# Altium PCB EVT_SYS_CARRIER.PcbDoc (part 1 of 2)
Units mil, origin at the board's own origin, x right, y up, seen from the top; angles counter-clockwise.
Board outline 3543.31 x 2755.91 mil, 4 copper layers (Top Layer, Mid-Layer 1, Mid-Layer 2, Bottom Layer), stack 63.036 mil thick; 105 components, 66 nets, 607 pads, 200 vias.
Unrouted connection lines stored in the file: 138.
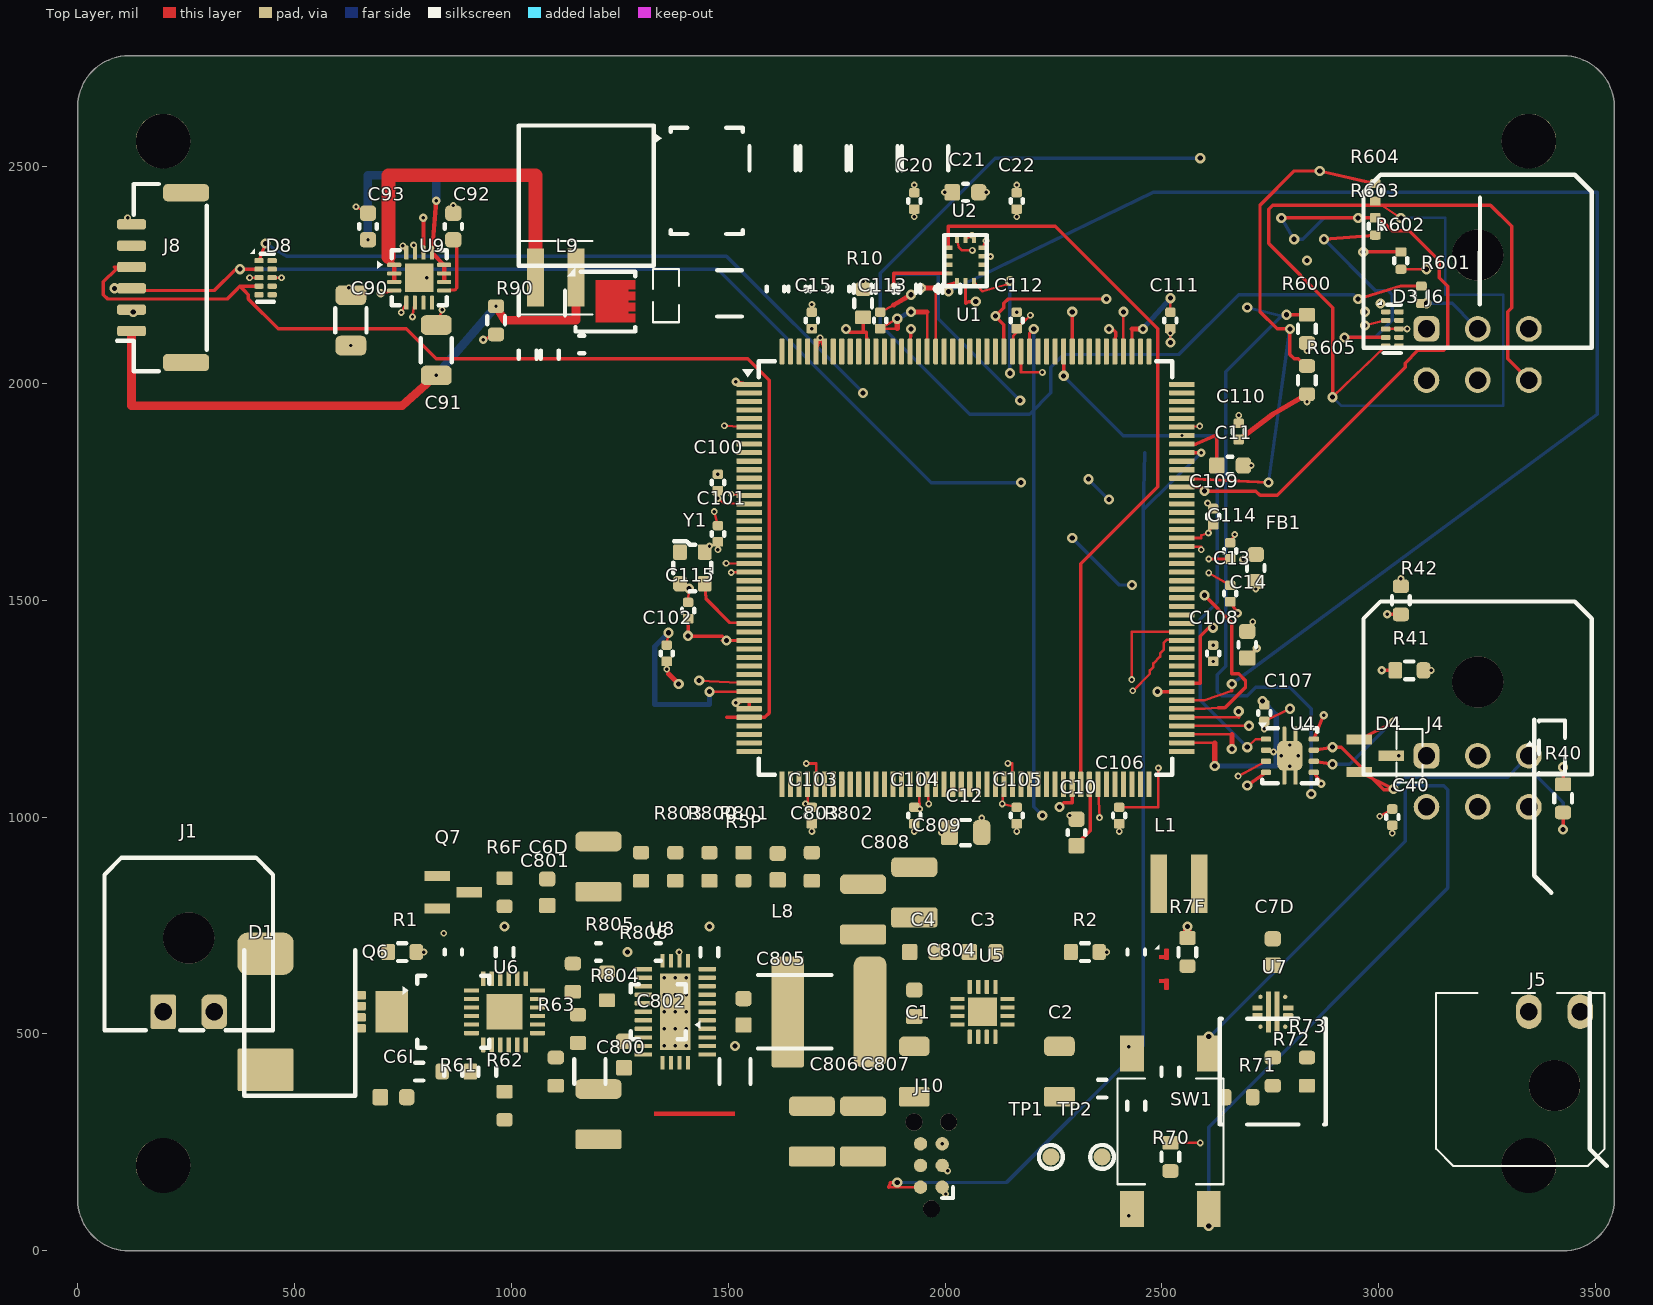
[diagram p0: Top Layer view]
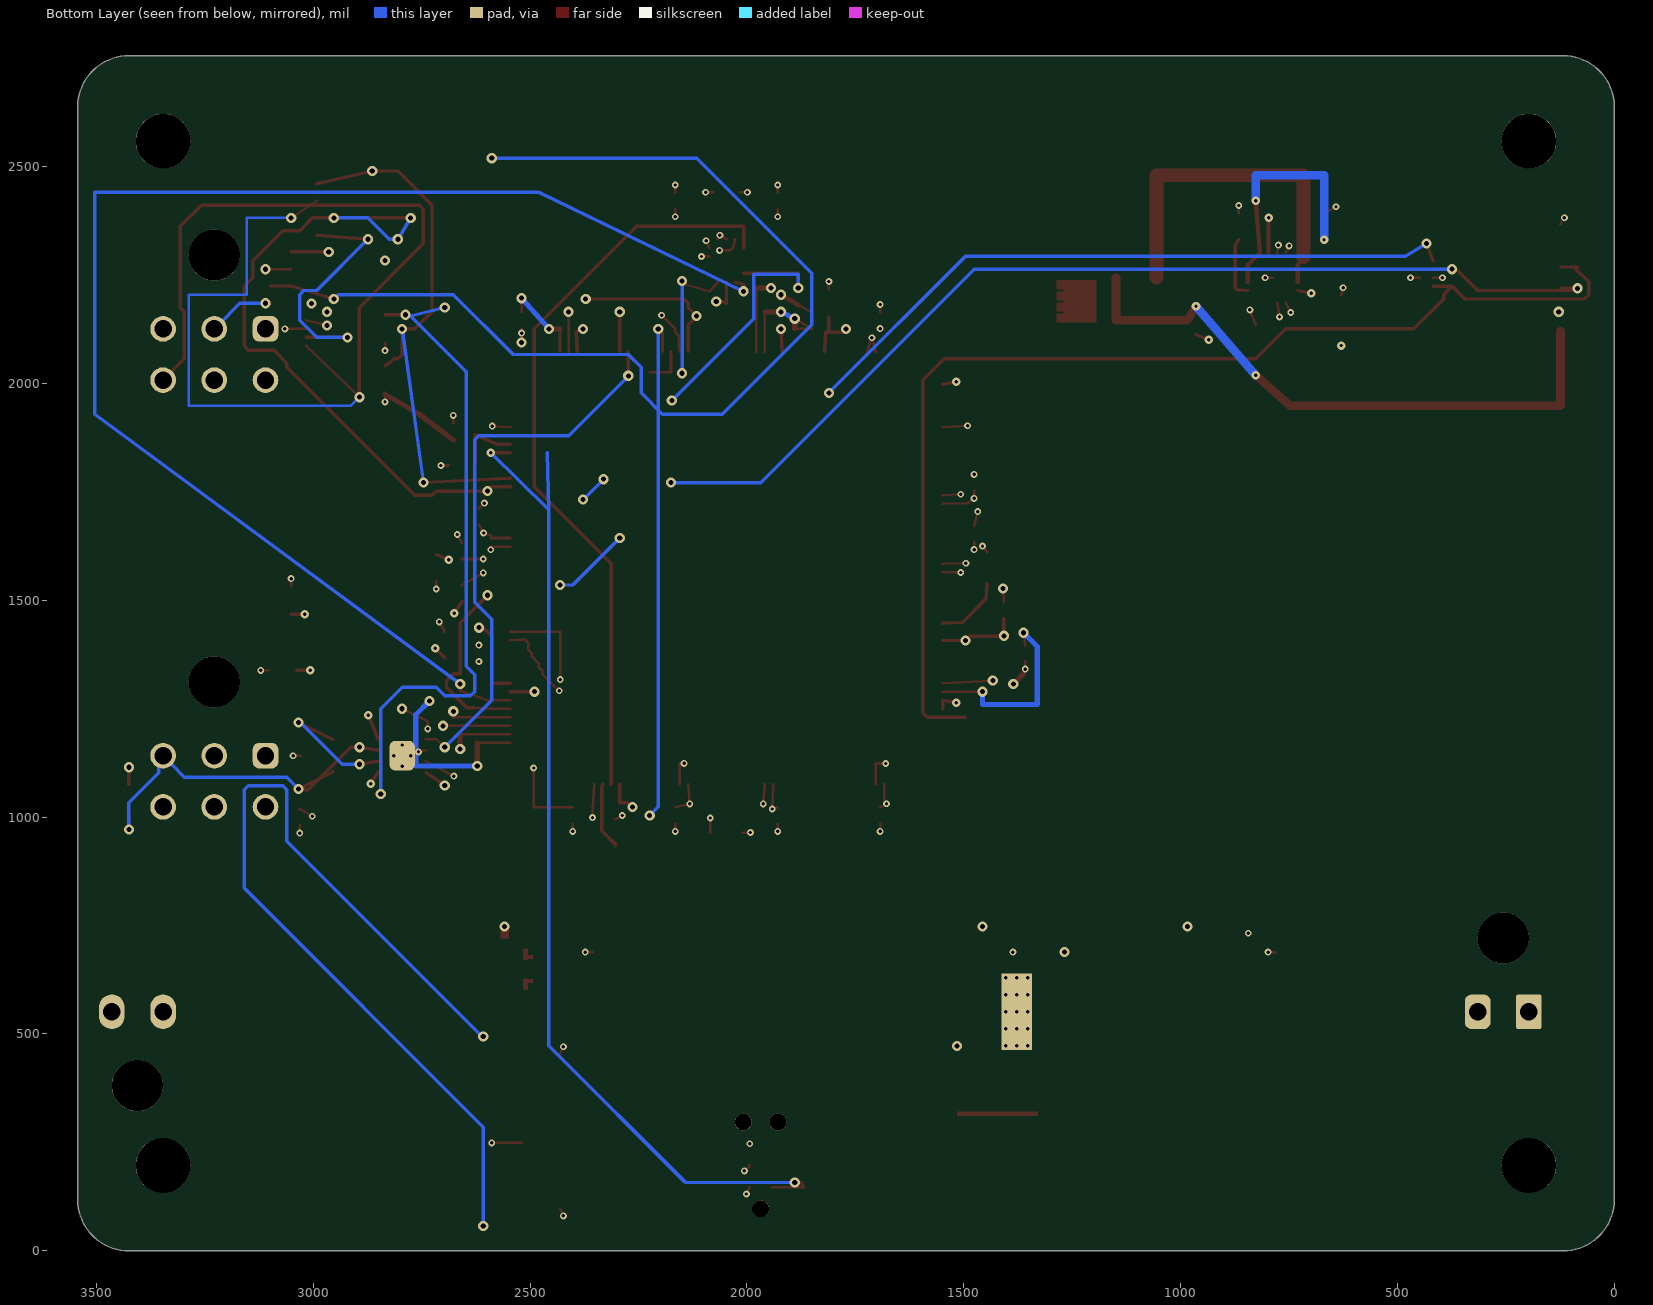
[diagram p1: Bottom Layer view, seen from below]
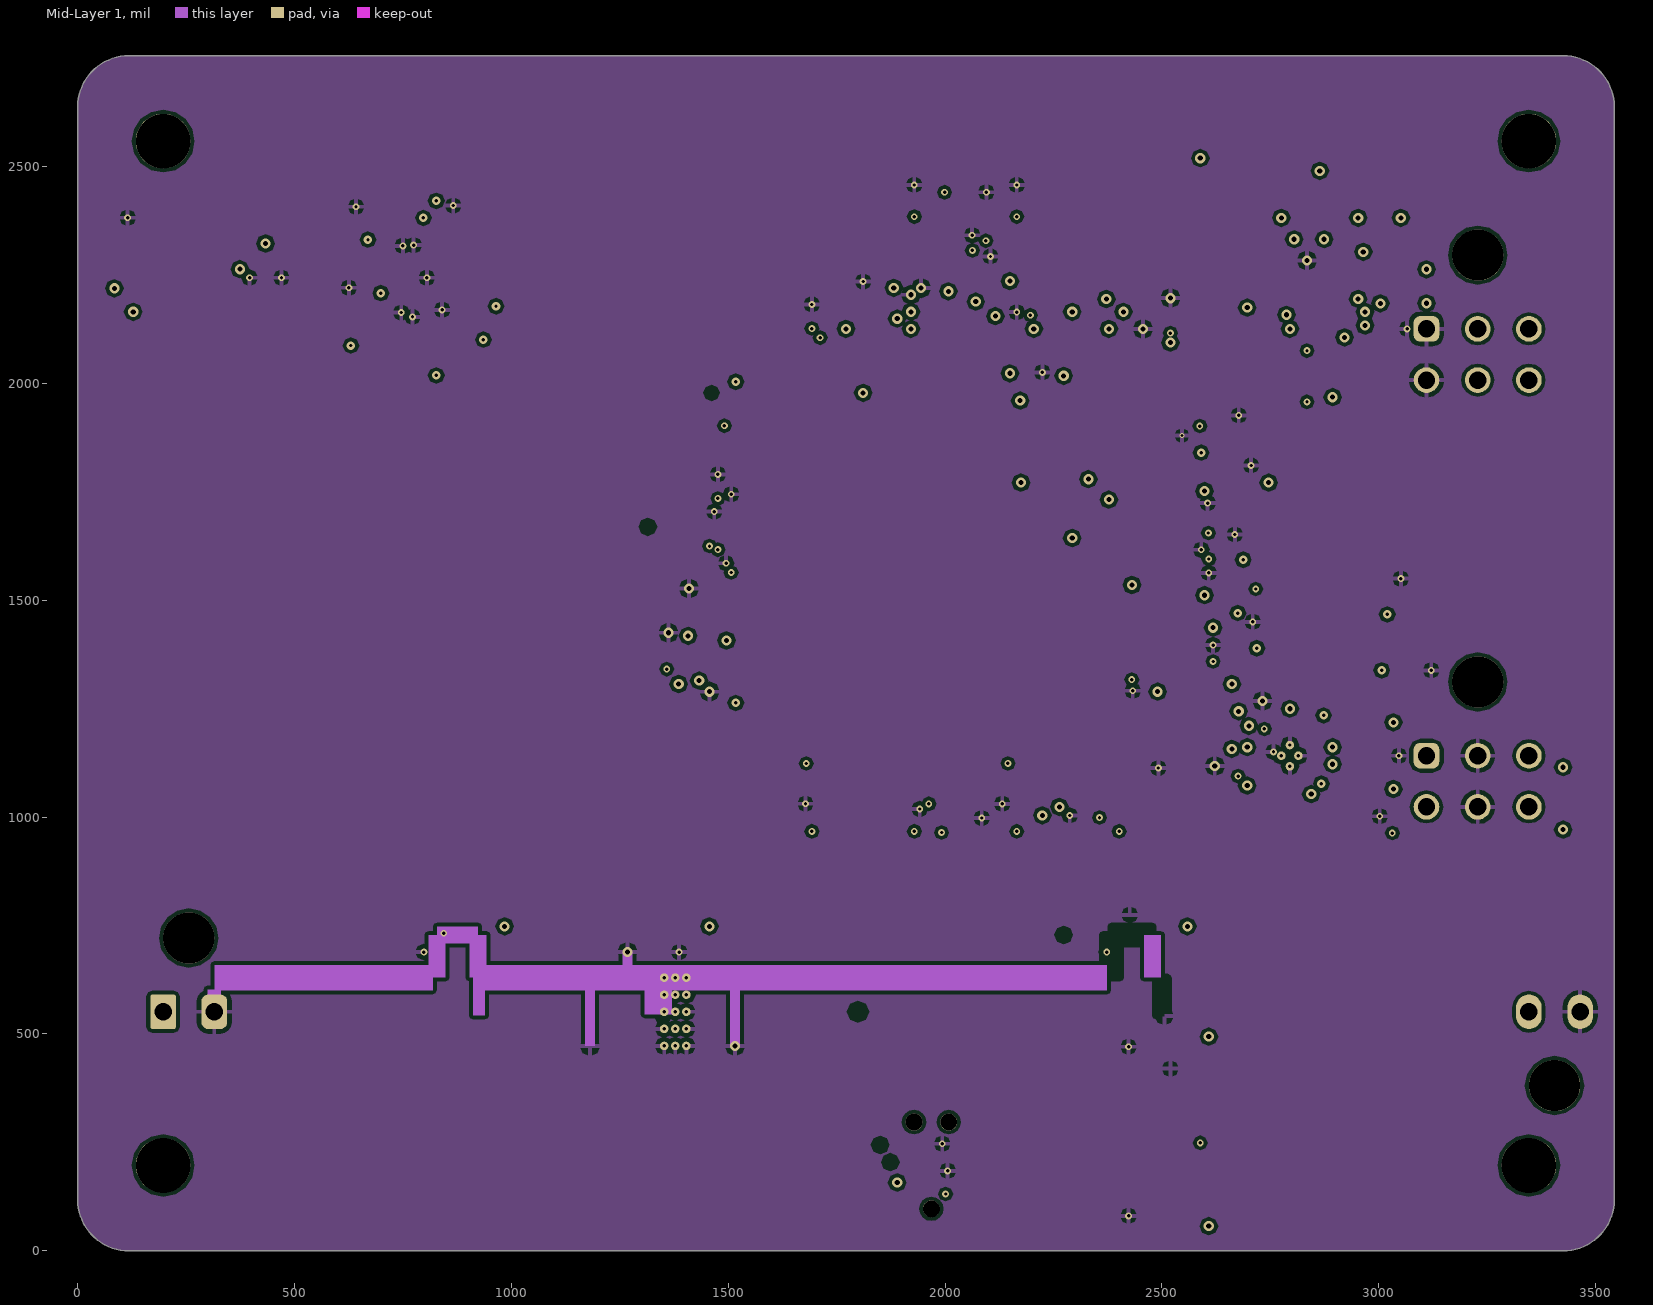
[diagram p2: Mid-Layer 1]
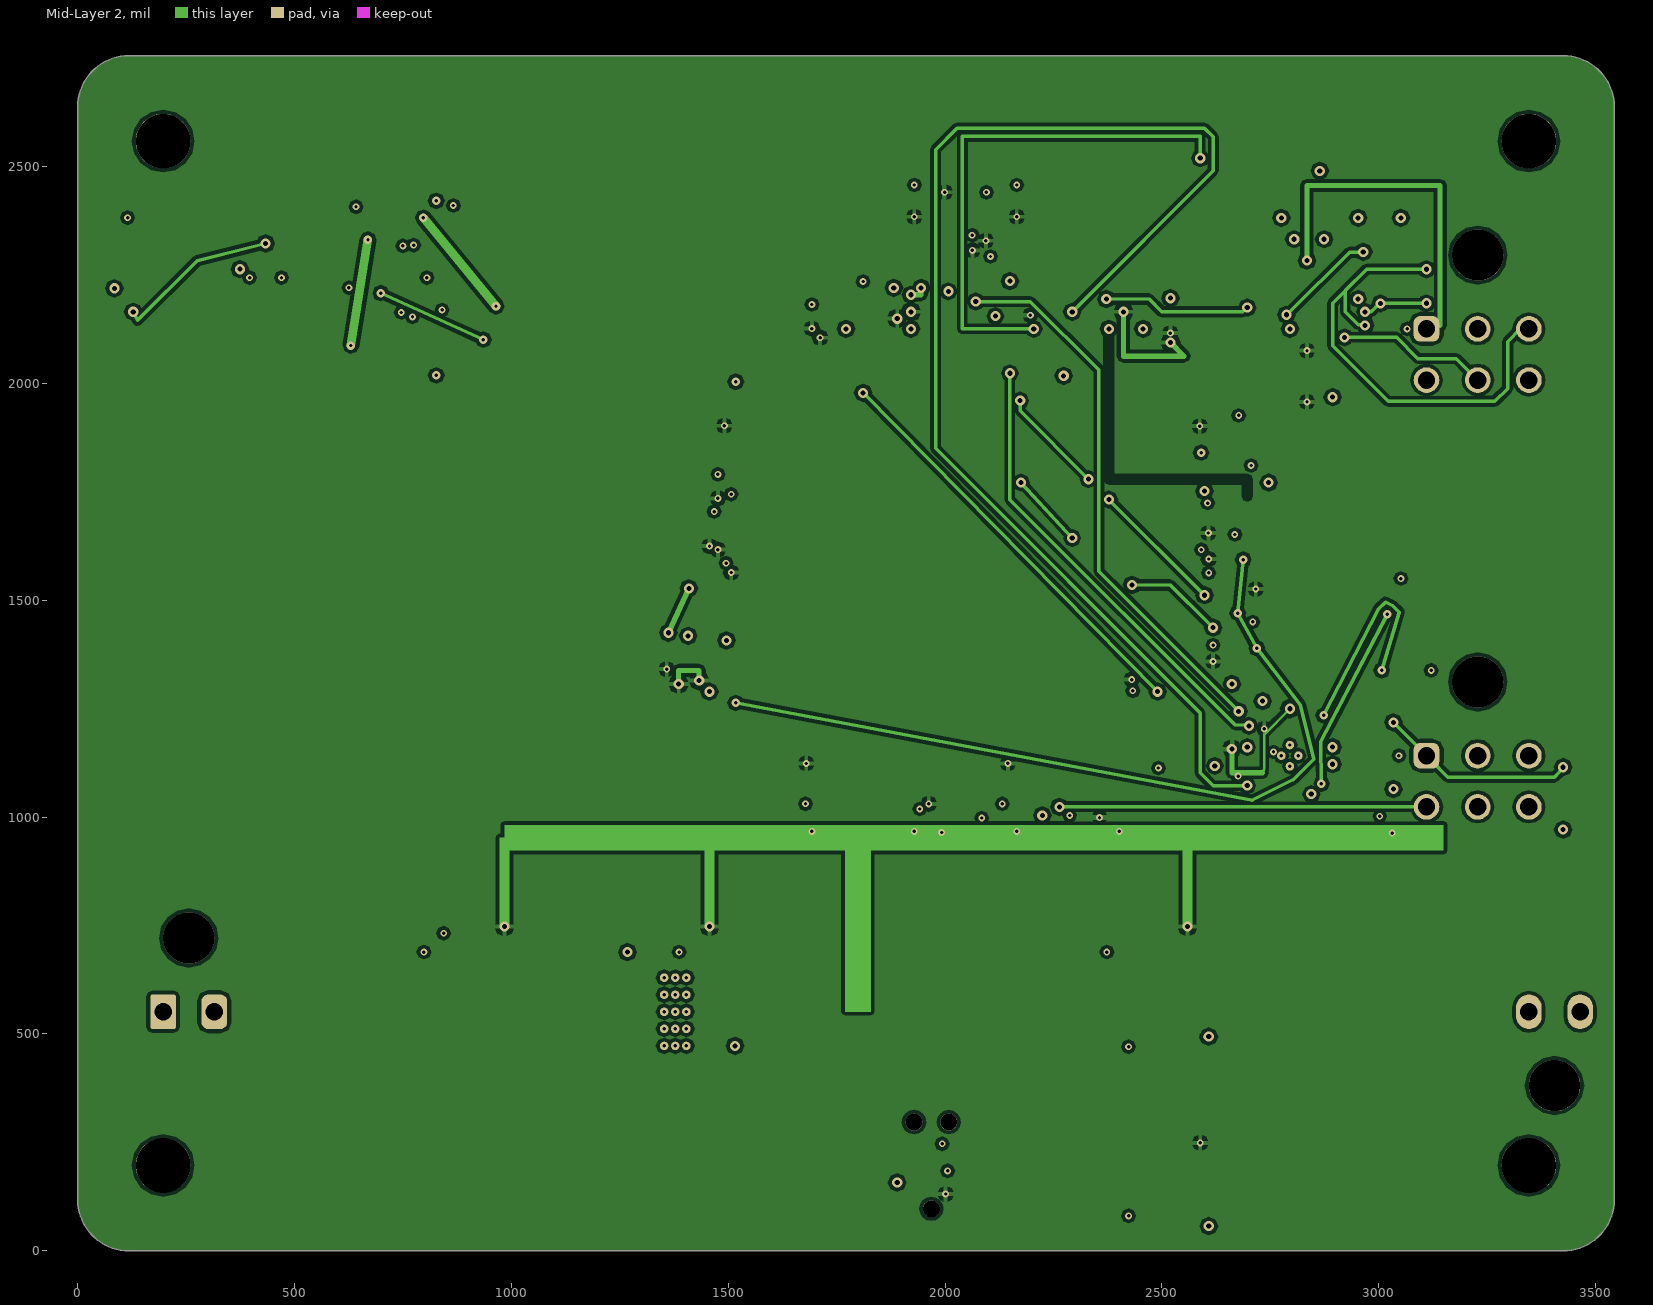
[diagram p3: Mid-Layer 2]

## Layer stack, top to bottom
Top Solder: solder mask 0.4, Solder Resist, Dk 3.5
Top Layer: signal copper 1.4
Dielectric 2: prepreg 7.0866, PP-006, Dk 4.2
Mid-Layer 1: signal copper 1.378
Dielectric 1: dielectric 43.3071, FR-4, Dk 4.2
Mid-Layer 2: signal copper 1.378
Dielectric 3: prepreg 7.0866, PP-006, Dk 4.2
Bottom Layer: signal copper 1.4
Bottom Solder: solder mask 0.4, Solder Resist, Dk 3.5

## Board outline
118.11,0 cw(c118.11,118.11) 0,118.11 0,2637.8 cw(c118.11,2637.8) 118.11,2755.91 3425.2,2755.91 cw(c3425.2,2637.8) 3543.31,2637.8 3543.31,118.11 cw(c3425.2,118.11) 3425.2,0

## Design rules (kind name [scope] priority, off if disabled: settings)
Clearance R_UART_TO_SW_CLEARANCE [InNetClass('NC_HOST_UART') Or InNetClass('NC_GNSS_UART') vs InNet('U8_SW') Or InNet('BUCK_SW') Or InNet('BUCK5_SW')] p1: gap=39.37 ignorepadtopadclearanceinfootprint=FALSE // EVT routing contract
Clearance R_FINE_PITCH_CLEARANCE [(InComponent('U6') Or InComponent('U7') Or InComponent('U8') Or InComponent('Q6') Or InComponent('D8')) vs (InComponent('U6') Or InComponent('U7') Or InComponent('U8') Or InComponent('Q6') Or InComponent('D8'))] p2: gap=5.12 ignorepadtopadclearanceinfootprint=FALSE // Footprint-defined fine-pitch clearance; fabricator confirmation deferred
Clearance R_TIMING_TO_SW_CLEARANCE [InNetClass('NC_TIMING') vs InNet('U8_SW') Or InNet('BUCK_SW') Or InNet('BUCK5_SW')] p3: gap=39.37 ignorepadtopadclearanceinfootprint=FALSE // EVT routing contract
Clearance R_GENERAL_CLEARANCE [All] p4: gap=7.87 ignorepadtopadclearanceinfootprint=FALSE // EVT routing contract
Clearance [All] p5: gap=10 ignorepadtopadclearanceinfootprint=FALSE
ComponentClearance [All] p1 off: gap=7.87 collisioncheckmode=3 verticalgap=7.87 showdistances=FALSE // Disabled: imported body extents are not assembly courtyards; see placement review evidence
DiffPairsRouting R_CAN_DIFF [InDifferentialPairClass('DP_CAN')] p1: maxlimit=11.81 minlimit=7.87 mostfreqgap=7.87 toplayer_minwidth=7.87 toplayer_maxwidth=11.81 toplayer_prefwidth=7.87 midlayer1_minwidth=7.87 midlayer1_maxwidth=11.81 midlayer1_prefwidth=7.87 midlayer2_minwidth=7.87 midlayer2_maxwidth=11.81 midlayer2_prefwidth=7.87 bottomlayer_minwidth=7.87 bottomlayer_maxwidth=11.81 bottomlayer_prefwidth=7.87 maxuncoupledlength=500 // EVT routing contract
DiffPairsRouting [All] p2: maxlimit=10 minlimit=10 mostfreqgap=10 toplayer_minwidth=15 toplayer_maxwidth=15 toplayer_prefwidth=15 midlayer1_minwidth=15 midlayer1_maxwidth=15 midlayer1_prefwidth=15 midlayer2_minwidth=15 midlayer2_maxwidth=15 midlayer2_prefwidth=15 bottomlayer_minwidth=15 bottomlayer_maxwidth=15 bottomlayer_prefwidth=15 maxuncoupledlength=500
HoleSize [All] p1: absolutevalues=TRUE maxlimit=129.92 minlimit=7.09 maxpercent=80.000 minpercent=20.000 // Standard PTH and 3.2/3.25mm mechanical holes
PolygonConnect [All] p1: connectstyle=Relief reliefconductorwidth=10 reliefentries=4 polygonreliefangle="90 Angle" airgapwidth=10
RoutingVias [All] p1: holewidth=28 width=50 viastyle="Through Hole" minholewidth=28 minwidth=50 maxholewidth=28 maxwidth=50
SolderMaskExpansion [All] p1: expansion=0 istentingtop=FALSE
Width R_V12_SYS_WIDTH [InNet('V12_SYS')] p1: maxlimit=196.85 minlimit=118.11 preferedwidth=118.11 // EVT routing contract
Width R_5V_GNSS_WIDTH [InNet('5V_GNSS')] p2: maxlimit=59.06 minlimit=19.68 preferedwidth=29.53 // EVT routing contract
Width R_3V3_TRUNK_WIDTH [InNet('3V3')] p3: maxlimit=118.11 minlimit=59.06 preferedwidth=59.06 // EVT routing contract
Width R_RADAR_12V_WIDTH [InNet('RADAR_12V')] p4: maxlimit=118.11 minlimit=59.06 preferedwidth=59.06 // EVT routing contract
Width R_VIN_HIGH_CURRENT [InNet('VIN_RAW') Or InNet('VIN_PROTECTED_24V')] p5: maxlimit=196.85 minlimit=118.11 preferedwidth=118.11 // EVT routing contract
Width R_GNSS_RF_WIDTH [InNet('GNSS_RF')] p6: maxlimit=14.17 minlimit=14.17 preferedwidth=14.17
Width R_GENERAL_WIDTH [All] p7: maxlimit=19.68 minlimit=5.91 preferedwidth=7.87 // EVT routing contract
27 further rules are at their usual default settings.

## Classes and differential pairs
net class NC_IMU_SPI: IMU_MISO IMU_MOSI IMU_NSS IMU_SCK
net class NC_GNSS_UART: GNSS_RX_EXT GNSS_TX_EXT
net class NC_HOST_UART: HOST_UART1_RX HOST_UART1_RX_EXT HOST_UART1_TX HOST_UART1_TX_EXT HOST_UART2_RX HOST_UART2_RX_EXT HOST_UART2_TX HOST_UART2_TX_EXT
net class NC_TIMING: GNSS_PPS IMU_DRDY RADAR_REF
net class NC_CAN: RADAR_CANH RADAR_CANL
net class NC_POWER_5V_GNSS: 5V_GNSS
net class NC_POWER_3V3: 3V3 VDDA_FILTERED
net class NC_POWER_12V: RADAR_12V V12_SYS
net class NC_POWER_24V: VIN_PROTECTED_24V VIN_RAW
differential pair class DP_CAN: DP_CAN
component class TIME_GNSS: D8 J8
component class DEBUG_BOOT: R70 SW1
component class HOST_UART: D3 J6 R600 R601 R602 R603 R604 R605
component class RADAR_IO_CAN: C40 D4 J4 J5 R40 R41 R42 U4
component class IMU: C20 C21 C22 U2
component class MCU_CORE: C10 C11 C12 C13 C14 C15 C100 C101 C102 C103 C104 C105 C106 C107 C108 C109 C110 C111 C112 C113 C114 C115 FB1 J10 R10 TP1 TP2 U1 Y1
component class POWER_INPUT: C1 C2 C3 C4 C6D C6I C7D C90 C91 C92 C93 C800 C801 C802 C803 C804 C805 C806 C807 C808 C809 D1 J1 L1 L8 L9 Q6 Q7 R1 R2 R5P R6F R7F R61 R62 R63 R71 R72 R73 R90 R800 R801 R802 R803 R804 R805 R806 U5 U6 U7 U8 U9
differential pair DP_CAN: +RADAR_CANH -RADAR_CANL

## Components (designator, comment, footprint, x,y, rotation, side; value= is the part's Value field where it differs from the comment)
C1 "10uF/25V" C_1206_3216Metric#1 1929.13,413.39 r90 top
C2 "22uF/6.3V" C_1206_3216Metric#1 2263.78,413.39 r90 top
C3 "3.3nF" C_0603_1608Metric#1 2086.61,688.98 r0 top
C4 "100nF/25V" C_0603_1608Metric#1 1948.82,688.98 r0 top
C6D "100nF" C_0603_1608Metric#1 1082.68,826.77 r90 top
C6I "100nF/100V" C_0603_1608Metric#1 728.35,354.33 r0 top
C7D "3.3nF" C_0603_1608Metric#1 2755.91,688.98 r90 top
C10 "2.2uF" C_0603_1608Metric#1 2303.15,964.57 r90 top
C11 "2.2uF" C_0603_1608Metric#1 2657.48,1811.02 r0 top
C12 "4.7uF" C_0805_2012Metric 2047.24,964.57 r0 top
C13 "100nF" C_0402_1005Metric#1 2657.48,1515.75 r90 top
C14 "1uF" C_0603_1608Metric#1 2696.85,1397.64 r90 top
C15 "100nF" C_0402_1005Metric#1 1692.91,2145.67 r90 top
C20 "100nF" C_0402_1005Metric#1 1929.13,2421.26 r90 top
C21 "2.2uF" C_0603_1608Metric#1 2047.24,2440.94 r0 top
C22 "10nF" C_0402_1005Metric#1 2165.35,2421.26 r90 top
C40 "100nF" C_0402_1005Metric#2 3031.5,1000 r180 top
C90 "10uF/25V" C_1206_3216Metric#2 629.92,2145.67 r0 top
C91 "22uF/10V" C_1206_3216Metric#3 800,1881.1 r0 top
C92 "3.3nF" C_0603_1608Metric#2 866.14,2362.2 r0 top
C93 "100nF/25V" C_0603_1608Metric#2 669.29,2362.2 r0 top
C100 "100nF VDD" C_0402_1005Metric#1 1476.38,1771.65 r90 top
C101 "100nF VDD" C_0402_1005Metric#1 1476.38,1653.54 r90 top
C102 "100nF VDD" C_0402_1005Metric#1 1358.27,1377.95 r90 top
C103 "100nF VDD" C_0402_1005Metric#1 1692.91,1003.94 r90 top
C104 "100nF VDD" C_0402_1005Metric#1 1929.13,1003.94 r90 top
C105 "100nF VDD" C_0402_1005Metric#1 2165.35,1003.94 r90 top
C106 "100nF VDD" C_0402_1005Metric#1 2401.57,1003.94 r90 top
C107 "100nF VDD" C_0402_1005Metric#2 2736.22,1240.16 r180 top
C108 "100nF VDD" C_0402_1005Metric#1 2618.11,1377.95 r90 top
C109 "100nF VDD" C_0402_1005Metric#1 2618.11,1692.91 r90 top
C110 "100nF VDD" C_0402_1005Metric#1 2677.17,1889.76 r90 top
C111 "100nF VDD" C_0402_1005Metric#1 2519.69,2145.67 r90 top
C112 "100nF VDD" C_0402_1005Metric#1 2165.35,2145.67 r90 top
C113 "100nF VDD" C_0402_1005Metric#1 1850.39,2145.67 r90 top
C114 "100nF VDD33_USB" C_0402_1005Metric#1 2657.48,1614.17 r90 top
C115 "100nF NRST" C_0402_1005Metric#1 1407.48,1476.38 r90 top
C800 "4.7uF/100V" C_1210_3225Metric 1200.79,314.96 r90 top
C801 "4.7uF/100V" C_1210_3225Metric 1200.79,885.83 r90 top
C802 "47nF/100V" C_0603_1608Metric#1 1259.84,452.76 r90 top
C803 "2.2uF/10V" C_0603_1608Metric#1 1614.17,885.83 r90 top
C804 "1uF/25V" C_0603_1608Metric#1 1929.13,570.87 r90 top
C805 "470nF/25V" C_0603_1608Metric#1 1535.43,551.18 r90 top
C806 "47uF/25V" C_1210_3225Metric 1692.91,275.59 r90 top
C807 "47uF/25V" C_1210_3225Metric 1811.02,275.59 r90 top
C808 "47uF/25V" C_1210_3225Metric 1811.02,787.4 r90 top
C809 "47uF/25V" C_1210_3225Metric 1929.13,826.77 r90 top
D1 "SMCJ36CA" D_SMC 433.07,551.18 r90 top
D3 "DUAL_UART_ESD" USON-10_2.5x1.0mm_P0.5mm 3031.5,2125.98 r0 top
D4 "CAN_ESD" SOT-23 2992.13,1141.73 r0 top
D8 "UART_PPS_ESD" USON-10_2.5x1.0mm_P0.5mm 433.07,2244.09 r0 top
FB1 "BLM18BD601SH1" L_0603_1608Metric 2716.54,1574.8 r90 top
J1 "24V_IN" Molex_43650-0200_RA_THT_2P#1 196.85,551.18 r0 top
J4 "RADAR_IO" Molex_43045-0600_RA_THT_6P 3110.24,1141.73 r0 top
J5 "RADAR_PWR" Molex_43650-0200_RA_THT_2P#2 3346.46,551.18 r0 top
J6 "HOST_UART_2X" Molex_43045-0600_RA_THT_6P 3110.24,2125.98 r0 top
J8 "EXT_GNSS_PIXHAWK" JST_GH_SM06B-GHS-TB_1x06-1MP_P1.25mm_Horizontal 196.85,2244.09 r0 top
J10 "TC2030_SWD" TagConnect_TC2030_NL 1968.5,196.85 r90 top
L1 "2.2uH" Coilcraft_XFL4020_4x4 2539.37,846.46 r0 top
L8 "10uH XAL7070-103MEC" L_Coilcraft_XAL7070-XXX 1732.28,551.18 r0 top
L9 "2.2uH" Coilcraft_XFL4020_4x4 1102.36,2244.09 r0 top
Q6 "CSD19537Q3" VSON-8_3.3x3.3mm_P0.65mm_NexFET 708.66,551.18 r0 top
Q7 "BSS138" SOT-23 866.14,826.77 r0 top
R1 "4.02k 1%" R_0603_1608Metric#1 748.03,688.98 r0 top
R2 "1.05k 1%" R_0603_1608Metric#1 2322.83,688.98 r0 top
R5P "100k 1% PG_PU" R_0603_1608Metric#2 1535.43,885.83 r90 top
R6F "10k 1% FLT_PU" R_0603_1608Metric#2 984.25,826.77 r90 top
R7F "10k 1% FLT_PU" R_0603_1608Metric#2 2559.06,688.98 r90 top
R10 "10k 1%" R_0603_1608Metric#1 1811.02,2185.04 r90 top
R40 "120R" R_0603_1608Metric#2 3425.2,1043.31 r90 top
R41 "10k" R_0603_1608Metric#1 3070.87,1338.58 r0 top
R42 "10k" R_0603_1608Metric#3 3051.18,1500 r0 top
R61 "887k 1%" R_0603_1608Metric#2 873.03,413.39 r0 top
R62 "29.4k 1%" R_0603_1608Metric#2 984.25,334.65 r90 top
R63 "34.0k 1%" R_0603_1608Metric#1 1102.36,413.39 r90 top
R70 "0R" R_0603_1608Metric#2 2519.68,216.54 r90 top
R71 "470k 1%" R_0603_1608Metric#4 2677.17,354.33 r0 top
R72 "16.9k 1%" R_0603_1608Metric#4 2755.91,413.39 r90 top
R73 "43.7k 1%" R_0603_1608Metric#1 2834.65,413.39 r90 top
R90 "100k 1% PG_PU" R_0603_1608Metric#3 964.57,2145.67 r0 top
R600 "10k" R_0603_1608Metric#2 2834.65,2125.98 r90 top
R601 "33R" R_0402_1005Metric#1 3098.43,2204.72 r90 top
R602 "33R" R_0402_1005Metric#2 3051.18,2283.47 r90 top
R603 "33R" R_0402_1005Metric#2 2992.13,2362.2 r90 top
R604 "33R" R_0402_1005Metric#3 2992.13,2440.94 r90 top
R605 "10k" R_0603_1608Metric#3 2834.65,2007.87 r0 top
R800 "100k 1%" R_0603_1608Metric#1 1377.95,885.83 r90 top
R801 "9.09k 1%" R_0603_1608Metric#1 1456.69,885.83 r90 top
R802 "100k 1% RT" R_0603_1608Metric#1 1692.91,885.83 r90 top
R803 "100k 1% PG_PU" R_0603_1608Metric#1 1299.21,885.83 r90 top
R804 "499k 1%" R_0603_1608Metric#1 1153.54,511.81 r90 top
R805 "56.0k 1%" R_0603_1608Metric#1 1141.73,629.92 r90 top
R806 "100k 1%" R_0603_1608Metric#1 1220.47,610.24 r90 top
SW1 "NRST" ESwitch_TL3301_GullWing_6x6 2519.68,275.59 r0 top
TP1 "HOST_UART1_TX" TestPoint_Pad_D1.0mm 2244.09,216.54 r0 top
TP2 "HOST_UART1_RX" TestPoint_Pad_D1.0mm 2362.2,216.54 r0 top
U1 "STM32H753IIT6" LQFP-176_24x24mm_P0.5mm 2047.24,1574.8 r0 top
U2 "IMU" ICM-42688-P_LGA14_2.5x3mm_P0.5mm 2047.24,2283.46 r0 top
U4 "CAN_FD" Texas_DRB0008A 2795.28,1141.73 r0 top
U5 "3V3_BUCK" VQFN-16-1EP_3x3mm_P0.5mm_EP1.68x1.68mm#1 2086.61,551.18 r180 top
U6 "24V_SYS_EFUSE" Texas_RGE0024C_VQFN-24-1EP_4x4mm_P0.5mm_EP2.1x2.1mm 984.25,551.18 r0 top
U7 "RADAR_12V_EFUSE" TPS259470A_RPW0010A_VQFN-HR-10_2x2mm_P0.475mm 2755.91,551.18 r0 top
U8 "24V_TO_12V_5A" Texas_RNP0030B_WQFN-30-1EP_4x6mm_P0.5mm_EP1.8x4.5mm_ThermalVias 1377.95,551.18 r180 top
U9 "5V_GNSS_BUCK" VQFN-16-1EP_3x3mm_P0.5mm_EP1.68x1.68mm#2 787.4,2244.09 r0 top
Y1 "25MHz_OSC" Oscillator_SMD_ECS_2520MV-xxx-xx-4Pin_2.5x2.0mm 1417.32,1574.8 r0 top

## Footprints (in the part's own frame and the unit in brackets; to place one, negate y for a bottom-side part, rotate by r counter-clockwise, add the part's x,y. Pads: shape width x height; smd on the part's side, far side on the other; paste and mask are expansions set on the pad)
C_0402_1005Metric#1 [mm]
  rrect25% 0.56x0.62 smd: 1(-0.48,0)
  rrect50% 0.56x0.62 smd: 2(0.48,0)
C_0402_1005Metric#2 [mm]
  rrect50% 0.62x0.56 smd: 1(0,0.48) 2(0,-0.48)
C_0603_1608Metric#1 [mm]
  rrect25% 0.9x0.95 smd: 1(-0.775,0)
  rrect50% 0.9x0.95 smd: 2(0.775,0)
C_0603_1608Metric#2 [mm]
  rrect50% 0.95x0.9 smd: 1(0,-0.775) 2(0,0.775)
C_0805_2012Metric [mm]
  rrect25% 1x1.45 smd: 1(-0.95,0)
  rrect50% 1x1.45 smd: 2(0.95,0)
C_1206_3216Metric#1 [mm]
  rrect22% 1.15x1.8 smd: 1(-1.475,0)
  rrect50% 1.15x1.8 smd: 2(1.475,0)
C_1206_3216Metric#2 [mm]
  rrect50% 1.8x1.15 smd: 1(0,-1.475) 2(0,1.475)
C_1206_3216Metric#3 [mm]
  rrect50% 1.8x1.15 smd: 1(0.68,3.495) 2(0.68,6.445)
C_1210_3225Metric [mm]
  rrect22% 1.15x2.7 smd mask+0: 1(-1.475,0)
  rrect50% 1.15x2.7 smd mask+0: 2(1.475,0)
Coilcraft_XFL4020_4x4 [mm]
  rect 0.98x3.4 smd: 1(-1.185,0) 2(1.185,0)
D_SMC [mm]
  rrect10% 2.5x3.3 smd mask+0: 1(-3.4,0)
  rrect50% 2.5x3.3 smd mask+0: 2(3.4,0)
ESwitch_TL3301_GullWing_6x6 [mm] "E-Switch TL3301 series, 6 x 6 mm gull-wing tactile switch"
  rect 1.4x2.1 smd: 1(2.25,-4.55) 1(2.25,4.55) 2(-2.25,-4.55) 2(-2.25,4.55)
ICM-42688-P_LGA14_2.5x3mm_P0.5mm [mm]
  rect 0.475x0.25 smd: 1(-1.012,-0.75) 2(-1.012,-0.25) 3(-1.012,0.25) 4(-1.012,0.75) 8(1.012,0.75) 9(1.012,0.25) 10(1.012,-0.25) 11(1.012,-0.75)
  rect 0.25x0.475 smd: 5(-0.5,1.262) 6(0,1.262) 7(0.5,1.262) 12(0.5,-1.262) 13(0,-1.262) 14(-0.5,-1.262)
JST_GH_SM06B-GHS-TB_1x06-1MP_P1.25mm_Horizontal [mm]
  rrect50% 1.7x0.6 smd: 1(-1.85,-3.125) 2(-1.85,-1.875) 3(-1.85,-0.625) 4(-1.85,0.625) 5(-1.85,1.875) 6(-1.85,3.125)
  rrect50% 2.7x1 smd: MP(1.35,-4.975) MP(1.35,4.975)
L_0603_1608Metric [mm]
  rrect25% 0.875x0.95 smd: 1(-0.787,0)
  rrect50% 0.875x0.95 smd: 2(0.787,0)
L_Coilcraft_XAL7070-XXX [mm]
  rrect13% 1.92x6.5 smd mask+0: 1(-2.41,0)
  rrect50% 1.92x6.5 smd mask+0: 2(2.41,0)
LQFP-176_24x24mm_P0.5mm [mm]
  rrect25% 1.5x0.3 smd: 1(-12.675,10.75) 2(-12.675,10.25) 3(-12.675,9.75) 4(-12.675,9.25) 5(-12.675,8.75) 6(-12.675,8.25) 7(-12.675,7.75) 8(-12.675,7.25) 9(-12.675,6.75) 10(-12.675,6.25) 11(-12.675,5.75) 12(-12.675,5.25) 13(-12.675,4.75) 14(-12.675,4.25) 15(-12.675,3.75) 16(-12.675,3.25) 17(-12.675,2.75) 18(-12.675,2.25) 19(-12.675,1.75) 20(-12.675,1.25) 21(-12.675,0.75) 22(-12.675,0.25) 23(-12.675,-0.25) 24(-12.675,-0.75) 25(-12.675,-1.25) 26(-12.675,-1.75) 27(-12.675,-2.25) 28(-12.675,-2.75) 29(-12.675,-3.25) 30(-12.675,-3.75) 31(-12.675,-4.25) 32(-12.675,-4.75) 33(-12.675,-5.25) 34(-12.675,-5.75) 35(-12.675,-6.25) 36(-12.675,-6.75) 37(-12.675,-7.25) 38(-12.675,-7.75) 39(-12.675,-8.25) 40(-12.675,-8.75) 41(-12.675,-9.25) 42(-12.675,-9.75) 43(-12.675,-10.25) 44(-12.675,-10.75) 89(12.675,-10.75) 90(12.675,-10.25) 91(12.675,-9.75) 92(12.675,-9.25) 93(12.675,-8.75) 94(12.675,-8.25) 95(12.675,-7.75) 96(12.675,-7.25) 97(12.675,-6.75) 98(12.675,-6.25) 99(12.675,-5.75) 100(12.675,-5.25) 101(12.675,-4.75) 102(12.675,-4.25) 103(12.675,-3.75) 104(12.675,-3.25) 105(12.675,-2.75) 106(12.675,-2.25) 107(12.675,-1.75) 108(12.675,-1.25) 109(12.675,-0.75) 110(12.675,-0.25) 111(12.675,0.25) 112(12.675,0.75) 113(12.675,1.25) 114(12.675,1.75) 115(12.675,2.25) 116(12.675,2.75) 117(12.675,3.25) 118(12.675,3.75) 119(12.675,4.25) 120(12.675,4.75) 121(12.675,5.25) 122(12.675,5.75) 123(12.675,6.25) 124(12.675,6.75) 125(12.675,7.25) 126(12.675,7.75) 127(12.675,8.25) 128(12.675,8.75) 129(12.675,9.25) 130(12.675,9.75) 131(12.675,10.25) 132(12.675,10.75)
  rrect25% 0.3x1.5 smd: 45(-10.75,-12.675) 46(-10.25,-12.675) 47(-9.75,-12.675) 48(-9.25,-12.675) 49(-8.75,-12.675) 50(-8.25,-12.675) 51(-7.75,-12.675) 52(-7.25,-12.675) 53(-6.75,-12.675) 54(-6.25,-12.675) 55(-5.75,-12.675) 56(-5.25,-12.675) 57(-4.75,-12.675) 58(-4.25,-12.675) 59(-3.75,-12.675) 60(-3.25,-12.675) 61(-2.75,-12.675) 62(-2.25,-12.675) 63(-1.75,-12.675) 64(-1.25,-12.675) 65(-0.75,-12.675) 66(-0.25,-12.675) 67(0.25,-12.675) 68(0.75,-12.675) 69(1.25,-12.675) 70(1.75,-12.675) 71(2.25,-12.675) 72(2.75,-12.675) 73(3.25,-12.675) 74(3.75,-12.675) 75(4.25,-12.675) 76(4.75,-12.675) 77(5.25,-12.675) 78(5.75,-12.675) 79(6.25,-12.675) 80(6.75,-12.675) 81(7.25,-12.675) 82(7.75,-12.675) 83(8.25,-12.675) 84(8.75,-12.675) 85(9.25,-12.675) 86(9.75,-12.675) 87(10.25,-12.675) 88(10.75,-12.675) 133(10.75,12.675) 134(10.25,12.675) 135(9.75,12.675) 136(9.25,12.675) 137(8.75,12.675) 138(8.25,12.675) 139(7.75,12.675) 140(7.25,12.675) 141(6.75,12.675) 142(6.25,12.675) 143(5.75,12.675) 144(5.25,12.675) 145(4.75,12.675) 146(4.25,12.675) 147(3.75,12.675) 148(3.25,12.675) 149(2.75,12.675) 150(2.25,12.675) 151(1.75,12.675) 152(1.25,12.675) 153(0.75,12.675) 154(0.25,12.675) 155(-0.25,12.675) 156(-0.75,12.675) 157(-1.25,12.675) 159(-2.25,12.675) 160(-2.75,12.675) 161(-3.25,12.675) 162(-3.75,12.675) 163(-4.25,12.675) 164(-4.75,12.675) 165(-5.25,12.675) 166(-5.75,12.675) 167(-6.25,12.675) 168(-6.75,12.675) 169(-7.25,12.675) 170(-7.75,12.675) 171(-8.25,12.675) 172(-8.75,12.675) 173(-9.25,12.675) 174(-9.75,12.675) 175(-10.25,12.675) 176(-10.75,12.675)
  rrect50% 0.3x1.5 smd: 158(-1.75,12.675)
Molex_43045-0600_RA_THT_6P [mm]
  rrect50% 1.5x1.5 hole 1.02: 1(0,0)
  round 1.5 hole 1.02: 2(3,0) 3(6,0) 4(0,-3) 5(3,-3) 6(6,-3)
  round 3 hole 3: Un1(3,4.32)
Molex_43650-0200_RA_THT_2P#1 [mm]
  rrect17% 1.5x2.02 hole 1.02: 1(0,0)
  rrect50% 1.5x2.02 hole 1.02: 2(3,0)
  round 3 hole 3: Un1(1.5,4.32)
Molex_43650-0200_RA_THT_2P#2 [mm] "Molex Micro-Fit 3.0 43650-0200, 2-position right-angle THT"
  oval 1.5x2.02 hole 1.02: 1(0,0) 2(3,0)
  round 3 hole 3 unplated: ""(1.5,-4.32)
Oscillator_SMD_ECS_2520MV-xxx-xx-4Pin_2.5x2.0mm [mm]
  rrect25% 0.8x0.9 smd: 1(-0.725,0.925) 3(0.725,-0.925) 4(0.725,0.925)
  rrect50% 0.8x0.9 smd: 2(-0.725,-0.925)
R_0402_1005Metric#1 [mm]
  rrect50% 0.54x0.64 smd: 1(-0.51,0) 2(0.51,0)
R_0402_1005Metric#2 [mm]
  rrect50% 0.54x0.64 smd: 1(-0.51,0)
  rrect25% 0.54x0.64 smd: 2(0.51,0)
R_0402_1005Metric#3 [mm]
  rrect25% 0.54x0.64 smd: 1(-0.51,0)
  rrect50% 0.54x0.64 smd: 2(0.51,0)
R_0603_1608Metric#1 [mm]
  rrect25% 0.8x0.95 smd: 1(-0.825,0)
  rrect50% 0.8x0.95 smd: 2(0.825,0)
R_0603_1608Metric#2 [mm]
  rrect50% 0.8x0.95 smd: 1(-0.825,0)
  rrect25% 0.8x0.95 smd: 2(0.825,0)
R_0603_1608Metric#3 [mm]
  rrect50% 0.95x0.8 smd: 1(0,-0.825) 2(0,0.825)
R_0603_1608Metric#4 [mm]
  rrect50% 0.8x0.95 smd: 1(-0.825,0) 2(0.825,0)
SOT-23 [mm] "JEDEC TO-236 AB, three-pad SOT-23"
  rect 1.475x0.6 smd: 1(-0.937,-0.95) 2(-0.937,0.95) 3(0.937,0)
TagConnect_TC2030_NL [mil]
  round 31 smd: 1(-50,-25) 2(-50,25) 3(0,-25) 4(0,25) 5(50,-25) 6(50,25)
  round 39 hole 39: Un1(-100,0) Un2(100,40) Un3(100,-40)
TestPoint_Pad_D1.0mm [mm]
  round 1 smd: 1(0,0)
Texas_DRB0008A [mm]
  rrect50% 0.6x0.31 smd: 1(-1.4,0.975) 2(-1.4,0.325) 3(-1.4,-0.325) 4(-1.4,-0.975) 5(1.4,-0.975) 6(1.4,-0.325) 7(1.4,0.325) 8(1.4,0.975)
  round 0.5 hole 0.2: 9(-0.5,0) 9(0,-0.625) 9(0,0.625) 9(0.5,0)
  rrect50% 0.23x1.025 smd: 9(-0.325,-1.188) 9(-0.325,1.188) 9(0.325,-1.188) 9(0.325,1.188)
  rrect50% 1.5x1.75 smd: 9(0,0)
  rrect50% 1.5x1.75 smd far side: 9(0,0)
  rrect50% 0.23x0.725 on Top Paste: Un1(-0.325,1.337) Un2(-0.325,-1.337) Un4(0.325,1.337) Un5(0.325,-1.337)
  rrect50% 1.34x1.55 on Top Paste: Un3(0,0)
Texas_RGE0024C_VQFN-24-1EP_4x4mm_P0.5mm_EP2.1x2.1mm [mm]
  rrect25% 0.875x0.25 smd mask+0: 1(-1.937,1.25) 2(-1.937,0.75) 3(-1.937,0.25) 4(-1.937,-0.25) 5(-1.937,-0.75) 6(-1.937,-1.25) 13(1.937,-1.25) 14(1.937,-0.75) 15(1.937,-0.25) 16(1.937,0.25) 17(1.937,0.75) 18(1.937,1.25)
  rrect25% 0.25x0.875 smd mask+0: 7(-1.25,-1.937) 8(-0.75,-1.937) 9(-0.25,-1.937) 10(0.25,-1.937) 11(0.75,-1.937) 12(1.25,-1.937) 19(1.25,1.937) 20(0.75,1.937) 21(0.25,1.937) 22(-0.25,1.937) 23(-0.75,1.937) 24(-1.25,1.937)
  rect 2.1x2.1 smd paste-2.1 mask+0: 25(0,0)
  rrect50% 0.85x0.85 on Top Paste mask-0.85: Un1(-0.525,0.525) Un2(-0.525,-0.525) Un3(0.525,0.525) Un4(0.525,-0.525)
Texas_RNP0030B_WQFN-30-1EP_4x6mm_P0.5mm_EP1.8x4.5mm_ThermalVias [mm]
  rrect25% 1.025x0.25 smd mask+0: 1(-1.863,2.5) 2(-1.863,2) 3(-1.863,1.5) 4(-1.863,1) 5(-1.863,0.5) 6(-1.863,0) 7(-1.863,-0.5) 8(-1.863,-1) 9(-1.863,-1.5) 10(-1.863,-2) 11(-1.863,-2.5) 16(1.863,-2.5) 17(1.863,-2) 18(1.863,-1.5) 19(1.863,-1) 20(1.863,-0.5) 21(1.863,0) 22(1.863,0.5) 23(1.863,1) 24(1.863,1.5) 25(1.863,2) 26(1.863,2.5)
  rrect25% 0.25x0.775 smd mask+0: 12(-0.75,-2.987) 13(-0.25,-2.987) 14(0.25,-2.987) 15(0.75,-2.987) 27(0.75,2.987) 28(0.25,2.987) 29(-0.25,2.987) 30(-0.75,2.987)
  round 0.5 hole 0.2 paste-2539.97 mask-0.5: 31(-0.65,2) 31(-0.65,1) 31(-0.65,0) 31(-0.65,-1) 31(-0.65,-2) 31(0,2) 31(0,1) 31(0,0) 31(0,-1) 31(0,-2) 31(0.65,2) 31(0.65,1) 31(0.65,0) 31(0.65,-1) 31(0.65,-2)
  rect 1.8x4.5 smd paste-4.5 mask+0: 31(0,0)
  rect 1.8x4.5 smd far side paste-4.5 mask-4.5: 31(0,0)
  rrect50% 0.78x0.97 on Top Paste mask-0.97: Un1(-0.45,1.68) Un2(-0.45,0.56) Un3(-0.45,-0.56) Un4(-0.45,-1.68) Un5(0.45,1.68) Un6(0.45,0.56) Un7(0.45,-0.56) Un8(0.45,-1.68)
TPS259470A_RPW0010A_VQFN-HR-10_2x2mm_P0.475mm [mm]
  round 0.25 smd: 1(-0.725,0.875) 4(-0.725,-0.875) 7(0.725,-0.875) 10(0.725,0.875)
  rrect17% 0.6x0.3 smd: 2(-0.9,0.225) 3(-0.9,-0.225) 9(0.9,0.225)
  rrect17% 0.3x2.4 smd: 5(-0.25,0) 6(0.25,0)
  rrect50% 0.6x0.3 smd: 8(0.9,-0.225)
  rrect17% 0.3x1.05 on Top Paste: Un1(-0.25,0.675) Un2(-0.25,-0.675) Un3(0.25,0.675) Un4(0.25,-0.675)
USON-10_2.5x1.0mm_P0.5mm [mm]
  rrect50% 0.55x0.3 smd: 1(-0.385,1) 2(-0.385,0.5) 3(-0.385,0) 4(-0.385,-0.5) 5(-0.385,-1) 6(0.385,-1) 7(0.385,-0.5) 8(0.385,0) 9(0.385,0.5) 10(0.385,1)
VQFN-16-1EP_3x3mm_P0.5mm_EP1.68x1.68mm#1 [mm]
  rrect25% 0.825x0.25 smd: 1(-1.462,0.75) 2(-1.462,0.25) 3(-1.462,-0.25) 4(-1.462,-0.75) 9(1.462,-0.75) 10(1.462,-0.25) 11(1.462,0.25) 12(1.462,0.75)
  rrect25% 0.25x0.825 smd: 5(-0.75,-1.462) 6(-0.25,-1.462) 7(0.25,-1.462) 8(0.75,-1.462) 13(0.75,1.462) 14(0.25,1.462) 15(-0.25,1.462) 16(-0.75,1.462)
  rect 1.68x1.68 smd: 17(0,0)
  rrect25% 0.68x0.68 on Top Paste: Un1(-0.42,0.42) Un2(-0.42,-0.42) Un3(0.42,0.42) Un4(0.42,-0.42)
VQFN-16-1EP_3x3mm_P0.5mm_EP1.68x1.68mm#2 [mm]
  rrect50% 0.825x0.25 smd: 1(-1.462,0.75) 2(-1.462,0.25) 3(-1.462,-0.25) 4(-1.462,-0.75) 9(1.462,-0.75) 10(1.462,-0.25) 11(1.462,0.25) 12(1.462,0.75)
  rrect50% 0.25x0.825 smd: 5(-0.75,-1.462) 6(-0.25,-1.462) 7(0.25,-1.462) 8(0.75,-1.462) 13(0.75,1.462) 14(0.25,1.462) 15(-0.25,1.462) 16(-0.75,1.462)
  rect 1.68x1.68 smd: 17(0,0)
  rrect50% 0.68x0.68 on Top Paste: Un1(-0.42,0.42) Un2(-0.42,-0.42) Un3(0.42,0.42) Un4(0.42,-0.42)
VSON-8_3.3x3.3mm_P0.65mm_NexFET [mm]
  rrect25% 0.63x0.5 smd mask+0: 1(-1.44,0.97) 2(-1.44,0.33) 3(-1.44,-0.33) 4(-1.44,-0.97)
  rect 1.9x2.45 smd paste-2.45 mask+0: 5(0.385,0)
  rect 0.57x0.738 on Top Paste mask-0.738: Un1(-0.09,0.61) Un2(-0.09,-0.61) Un3(0.86,0.61) Un4(0.86,-0.61)
  rrect50% 0.63x0.5 on Top Paste mask-0.63: Un5(1.44,0.972) Un6(1.44,0.33) Un7(1.44,-0.33) Un8(1.44,-0.972)

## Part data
C1 C90: library part C, MPN=10uF_25V_X7R
C2: library part C, MPN=22uF_6.3V_X7R
C3 C7D C92: library part C, MPN=3.3nF_X7R
C4 C6D C93: library part C, MPN=100nF_25V_X7R
C6I: library part C, MPN=100nF_100V_X7R
C10 C11 C21: library part C, MPN=2.2uF_6.3V_X7R
C12: library part C, MPN=4.7uF_6.3V_X7R
C13 C15 C20 C40 C100 C101 C102 C103 C104 C105 C106 C107 C108 C109 C110 C111 C112 C113 C114 C115: library part C, MPN=100nF_6.3V_X7R
C14: library part C, MPN=1uF_6.3V_X7R
C22: library part C, MPN=10nF_6.3V_X7R
C91: library part C, MPN=22uF_10V_X7R
C800 C801: library part C, MPN=C3225X7S2A475K200AB
C802: library part C, MPN=47nF_100V_X7R
C803: library part C, MPN=2.2uF_10V_X7R
C804: library part C, MPN=1uF_25V_X7R
C805: library part C, MPN=470nF_25V_X7R
C806 C807 C808 C809: library part C, MPN=47uF_25V_X7R
D1: library part D_TVS
D3 D8: library part TPD4E05U06DQAR
D4: library part ESD2CANFD24DBZRQ1
FB1: library part L_Ferrite
J1 J5: library part Conn_01x02, MPN=43650-0200
J4 J6: library part Conn_01x06, MPN=43045-0600
J8: library part Conn_01x06, MPN=SM06B-GHS-TB(LF)(SN)
J10: library part Conn_01x06, MPN=TC2030-NL_TARGET
L1 L9: library part L, MPN=XFL4020-222MEC
L8: library part L, MPN=XAL7070-103MEC
R1: library part R, MPN=4.02k_1%
R2: library part R, MPN=1.05k_1%
R5P R90 R800 R802 R803 R806: library part R, MPN=100k_1%
R6F R7F R10 R41 R42 R600 R605: library part R, MPN=10k_1%
R40: library part R, MPN=120R_1%
R61: library part R, MPN=887k_1%
R62: library part R, MPN=29.4k_1%
R63: library part R, MPN=34.0k_1%
R70: library part R
R71: library part R, MPN=470k_1%
R72: library part R, MPN=16.9k_1%
R73: library part R, MPN=43.7k_1%
R601 R602 R603 R604: library part R, MPN=33R_1%
R801: library part R, MPN=9.09k_1%
R804: library part R, MPN=499k_1%
R805: library part R, MPN=56.0k_1%
SW1: library part SW_Push, MPN=TL3301NF160QG
TP1 TP2: library part TestPoint
U1: library part STM32H753IITx
U2: library part ICM-42688-P
U4: library part TCAN3404DRBRQ1
U5: library part TPS62132RGTR
U6: library part TPS26630RGER
U7: library part TPS259470ARPWR
U8: library part LM76005RNPR
U9: library part TPS62133RGTR
Y1: library part ECS-2520S33-250-FN-TR

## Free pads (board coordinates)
  round 125.98 hole 125.98 unplated: H1(196.85,196.85) H2(3346.46,196.85) H3(196.85,2559.06) H4(3346.46,2559.06)

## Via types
v1: diameter 23.62, hole 11.81, Top Layer to Bottom Layer, 90 vias
v2: diameter 15.75, hole 7.87, Top Layer to Bottom Layer, 89 vias
v3: diameter 19.68, hole 7.87, Top Layer to Bottom Layer, 18 vias
v4: diameter 15.75, hole 7.87, Top Layer to Mid-Layer 1, 2 vias
v5: diameter 11.81, hole 7.09, Top Layer to Mid-Layer 1, 1 vias

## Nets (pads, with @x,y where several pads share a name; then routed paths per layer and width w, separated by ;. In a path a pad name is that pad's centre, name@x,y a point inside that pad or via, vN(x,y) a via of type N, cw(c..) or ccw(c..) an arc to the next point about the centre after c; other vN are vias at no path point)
3V3: C2.1 C12.1 C15.1 C20.1 C21.1 C22.1 C40.1 C100.1 C101.1 C102.1 C103.1 C104.1 C105.1 C106.1 C107.1 C108.1 C109.1 C110.1 C111.1 C112.1 C113.1 C114.1 FB1.1 J10.1 L1.2 R5P.2 R6F.2 R7F.2 R70.2 R600.1 R605.1 R803.2 U1.6 U1.15 U1.23 U1.36 U1.49 U1.62 U1.72 U1.82 U1.91 U1.103 U1.114 U1.127 U1.136 U1.149 U1.159 U1.171 U1.172 U2.5 U2.8 U4.3 U5.14 Y1.4 | length 3249.2
  Top Layer w5.91: v2(1358.27,1341.34) C102.1@1358.27,1359.06 1362.2,1330.71 ; v1(1433.07,1314.96) U1.36@1548.23,1309.06 ; Y1.4@1445.87,1611.22 v2(1456.8,1625.16) ; v2(1476.38,1616.93) C101.1@1476.38,1634.65 ; C100.1@1476.38,1752.76 v2(1476.38,1735.04) 1491.16,1723.92 U1.15@1548.23,1722.44 ; v2(1491.22,1902.65) U1.6@1548.23,1899.61 ; v2(1506.9,1564.15) U1.23@1548.23,1564.96 ; v2(1679.97,1123.81) 1702.76,1123.81 U1.49@1702.76,1075.79 ; v2(1692.91,967.32) C103.1@1692.91,985.04 ; U1.172@1702.76,2073.82 v2(1712.07,2105.63) U1.171@1722.44,2073.82 ; 1889.76,2126.77 C113.1@1850.39,2126.77 v1(1889.76,2149.61) ; v2(1929.13,967.32) C104.1@1929.13,985.04 ; v2(1929.13,2384.65) C20.1@1929.13,2402.36 ; U1.62@1958.66,1075.79 v2(1962.56,1030.68) ; U1.159@1958.66,2073.82 1958.66,2165.35 ; v2(1992.13,964.57) C12.1@2009.84,964.57 ; J10.1@1993.5,146.85 v2(2001.43,131) ; v2(1999.02,2440.95) C21.1@2016.73,2440.94 ; U2.5@2027.56,2333.17 2031.5,2314.96 2039.37,2307.09 v2(2062.99,2307.09) ; U2.8@2087.11,2312.99 v2(2094.16,2329.24) ; v2(2145.08,1123.88) 2155.51,1123.88 U1.72@2155.51,1075.79 ; U1.149@2155.51,2073.82 2157.48,2086.61 2157.48,2110.24 2165.35,2118.11 2165.35,2125.98 v2(2196.85,2157.48) 2181.1,2141.73 C112.1@2165.35,2126.77 ; v2(2165.35,967.32) C105.1@2165.35,985.04 ; v2(2165.35,2384.65) C22.1@2165.35,2402.36 ; U1.82@2352.36,1075.79 v2(2356.3,999.04) ; v2(2401.57,967.32) C106.1@2401.57,985.04 ; U1.136@2411.42,2073.82 v1(2411.42,2165.35) ; v2(2430.64,1317.37) 2430.64,1427.16 U1.103@2546.26,1427.17 ; R70.2@2519.68,249.02 v2(2588.58,249.02) ; v1(2519.68,2094.49) C111.1@2519.69,2126.77 v2(2519.68,2116.14) ; U1.91@2546.26,1190.94 2661.42,1190.94 ; U1.114@2546.26,1643.7 2591.11,1643.7 2591.11,1649.89 v2(2607.28,1655.26) C109.1@2618.11,1674.02 ; U1.127@2546.26,1899.61 v2(2587.54,1901.81) ; v2(2608.27,1595.28) C114.1@2657.48,1595.28 ; v2(2675.89,1094.67) U4.3@2740.16,1128.94 ; v2(2716.53,1526.08) FB1.1@2716.54,1543.8 ; v2(2736.22,1203.54) C107.1@2736.22,1221.26 v1(2795.28,1250) ; v2(2834.64,1957.68) R605.1@2834.65,1975.39 ; v2(2834.65,2075.79) R600.1@2834.65,2093.5 ; v2(3031.5,963.39) C40.1@3031.5,981.1
  Top Layer w11.81: 1362.2,1330.71 v1(1385.83,1307.09) ; 1889.76,2126.77 v1(1889.76,2149.61) ; v1(1921.26,2165.35) 1958.66,2165.35 ; v1(2661.42,1157.48) 2661.42,1190.94 ; C110.1@2677.17,1870.08 2755.91,1929.13 R605.1@2834.65,1975.39
  Mid-Layer 2 w5.91: 2732.28,1102.36 2736.22,1112.2 2736.22,1190.94 v1(2795.28,1250)
  Mid-Layer 2 w11.81: v1(1385.83,1307.09) 1385.83,1338.58 1433.07,1338.58 v1(1433.07,1314.96) ; v1(2411.42,2165.35) 2411.42,2062.99 2551.18,2062.99 v1(2519.68,2094.49) ; v1(2661.42,1157.48) 2661.42,1102.36 2732.28,1102.36
  Bottom Layer w11.81: v1(1889.76,2149.61) v1(1921.26,2165.35)
  other v1: 984.25,748.03 1456.69,748.03 2559.06,748.03
  other v2: 2618.11,1359.06 1692.91,2126.77
5V_GNSS: C91.1 J8.1 L9.2 R90.2 U9.14 | length 1757.3
  Top Layer w9.84: U9.14@797.24,2301.67 v3(797.24,2381.89)
  Top Layer w19.68: J8.1@124.02,2121.06 124.02,1948.82 748.03,1948.82 v3(826.77,2018.7) ; v3(964.57,2178.15) 984.25,2145.67 1149.02,2145.67 L9.2@1149.02,2244.09
  Mid-Layer 2 w19.68: v3(797.24,2381.89) v3(964.57,2178.15)
  Bottom Layer w19.68: v3(826.77,2018.7) v3(964.57,2178.15)
BOOT0: R10.1 R70.1 U1.166 | length 179.5
  Top Layer w7.87: v1(1771.65,2125.98) 1779.53,2118.11 1811.02,2118.11 ; U1.166@1820.87,2073.82 1818.9,2118.11 1803.15,2118.11 1811.02,2118.11 ; 1811.02,2118.11 R10.1@1811.02,2152.56 1811.02,2118.11
BUCK5_SW: L9.1 U9.1 U9.2 U9.3 | length 825.9
  Top Layer w9.84: 716.54,2291.34 U9.1@729.82,2273.62 U9.3@729.82,2234.25
  Top Layer w31.5: 716.54,2291.34 716.54,2480.32 1055.71,2480.32 L9.1@1055.71,2244.09
BUCK_SW: L1.1 U5.1 U5.2 U5.3
CAN_RX: U1.142 U4.4 | length 3161.2
  Top Layer w7.87: U1.142@2293.31,2073.82 v1(2293.31,2165.35) ; v1(2696.85,1072.83) U4.4@2740.16,1103.35
  Mid-Layer 2 w7.87: v1(2293.31,2165.35) 2303.15,2175.2 2618.11,2490.16 2618.11,2568.9 2598.43,2588.58 2027.56,2588.58 1978.35,2539.37 1978.35,1850.39 2588.58,1240.16 2588.58,1102.36 2618.11,1072.83 2687.01,1072.83 v1(2696.85,1072.83)
CAN_TX: U1.143 U4.1 | length 1292.2
  Top Layer w5.91: v1(2696.85,1161.42) 2716.54,1180.12 U4.1@2740.16,1180.12
  Top Layer w7.87: v1(2273.62,2017.72) U1.143@2273.62,2073.82
  Bottom Layer w7.87: v1(2273.62,2017.72) 2283.46,2007.87 2411.42,1879.92 2618.11,1879.92 2627.95,1870.08 2627.95,1496.06 2588.58,1456.69 2588.58,1269.68 2687.01,1171.26 v1(2696.85,1161.42)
